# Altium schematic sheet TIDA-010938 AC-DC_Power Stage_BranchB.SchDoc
size 558 x 431 mm; Date: Not shown in title block; ApprovedBy: Not shown in title block; CheckedBy: Not shown in title block; Author: Not shown in title block; CompanyName: Not shown in title block; Engineer: Not shown in title block; Organization: Not shown in title block; Address1: Not shown in title block; Address2: Not shown in title block; Address3: Not shown in title block; Address4: Not shown in title block; DocumentNumber: 3; Revision: Use project parameter SCH_Rev; SheetNumber: 4; SheetTotal: 11; PageSetup: Record=PageOptions¦CenterHorizontal=True¦CenterVertical=True¦PrintScale=1.00¦XCorrection=1.00¦YCorrection=1.00¦PrintKind=0¦BorderSize=5000000¦LeftOffset=0¦BottomOffset=0¦Orientation=2¦PaperLength=1000¦PaperWidth=1000¦Scale=100¦PaperSource=15¦PrintQuality=600¦MediaType=1¦DitherType=10¦PaperKind=Letter¦PrintScaleMode=1
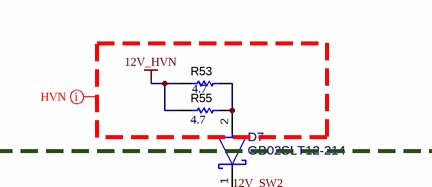
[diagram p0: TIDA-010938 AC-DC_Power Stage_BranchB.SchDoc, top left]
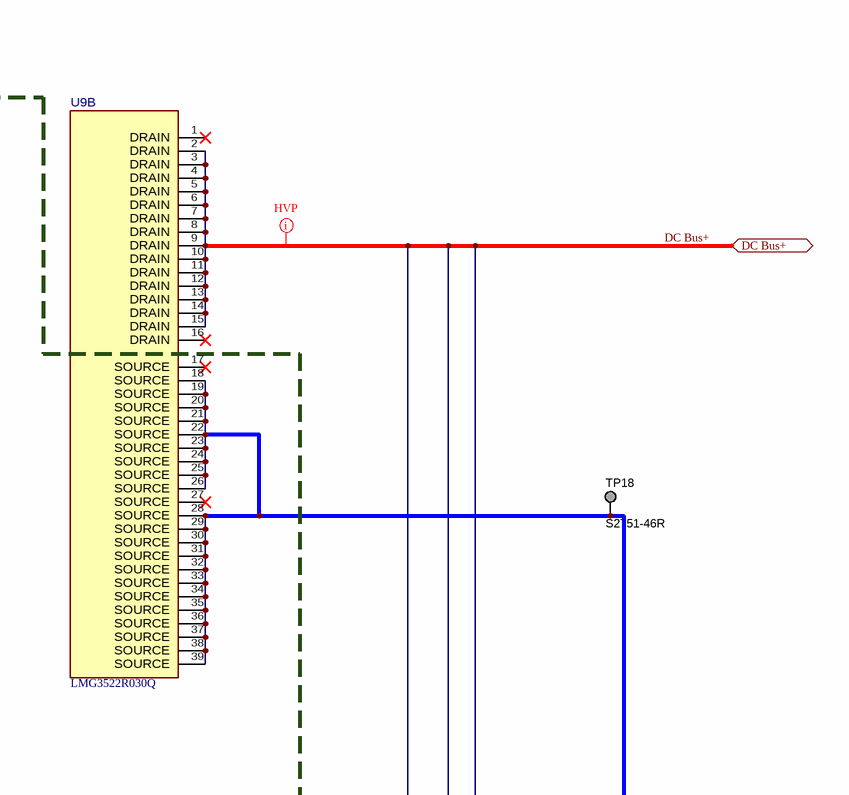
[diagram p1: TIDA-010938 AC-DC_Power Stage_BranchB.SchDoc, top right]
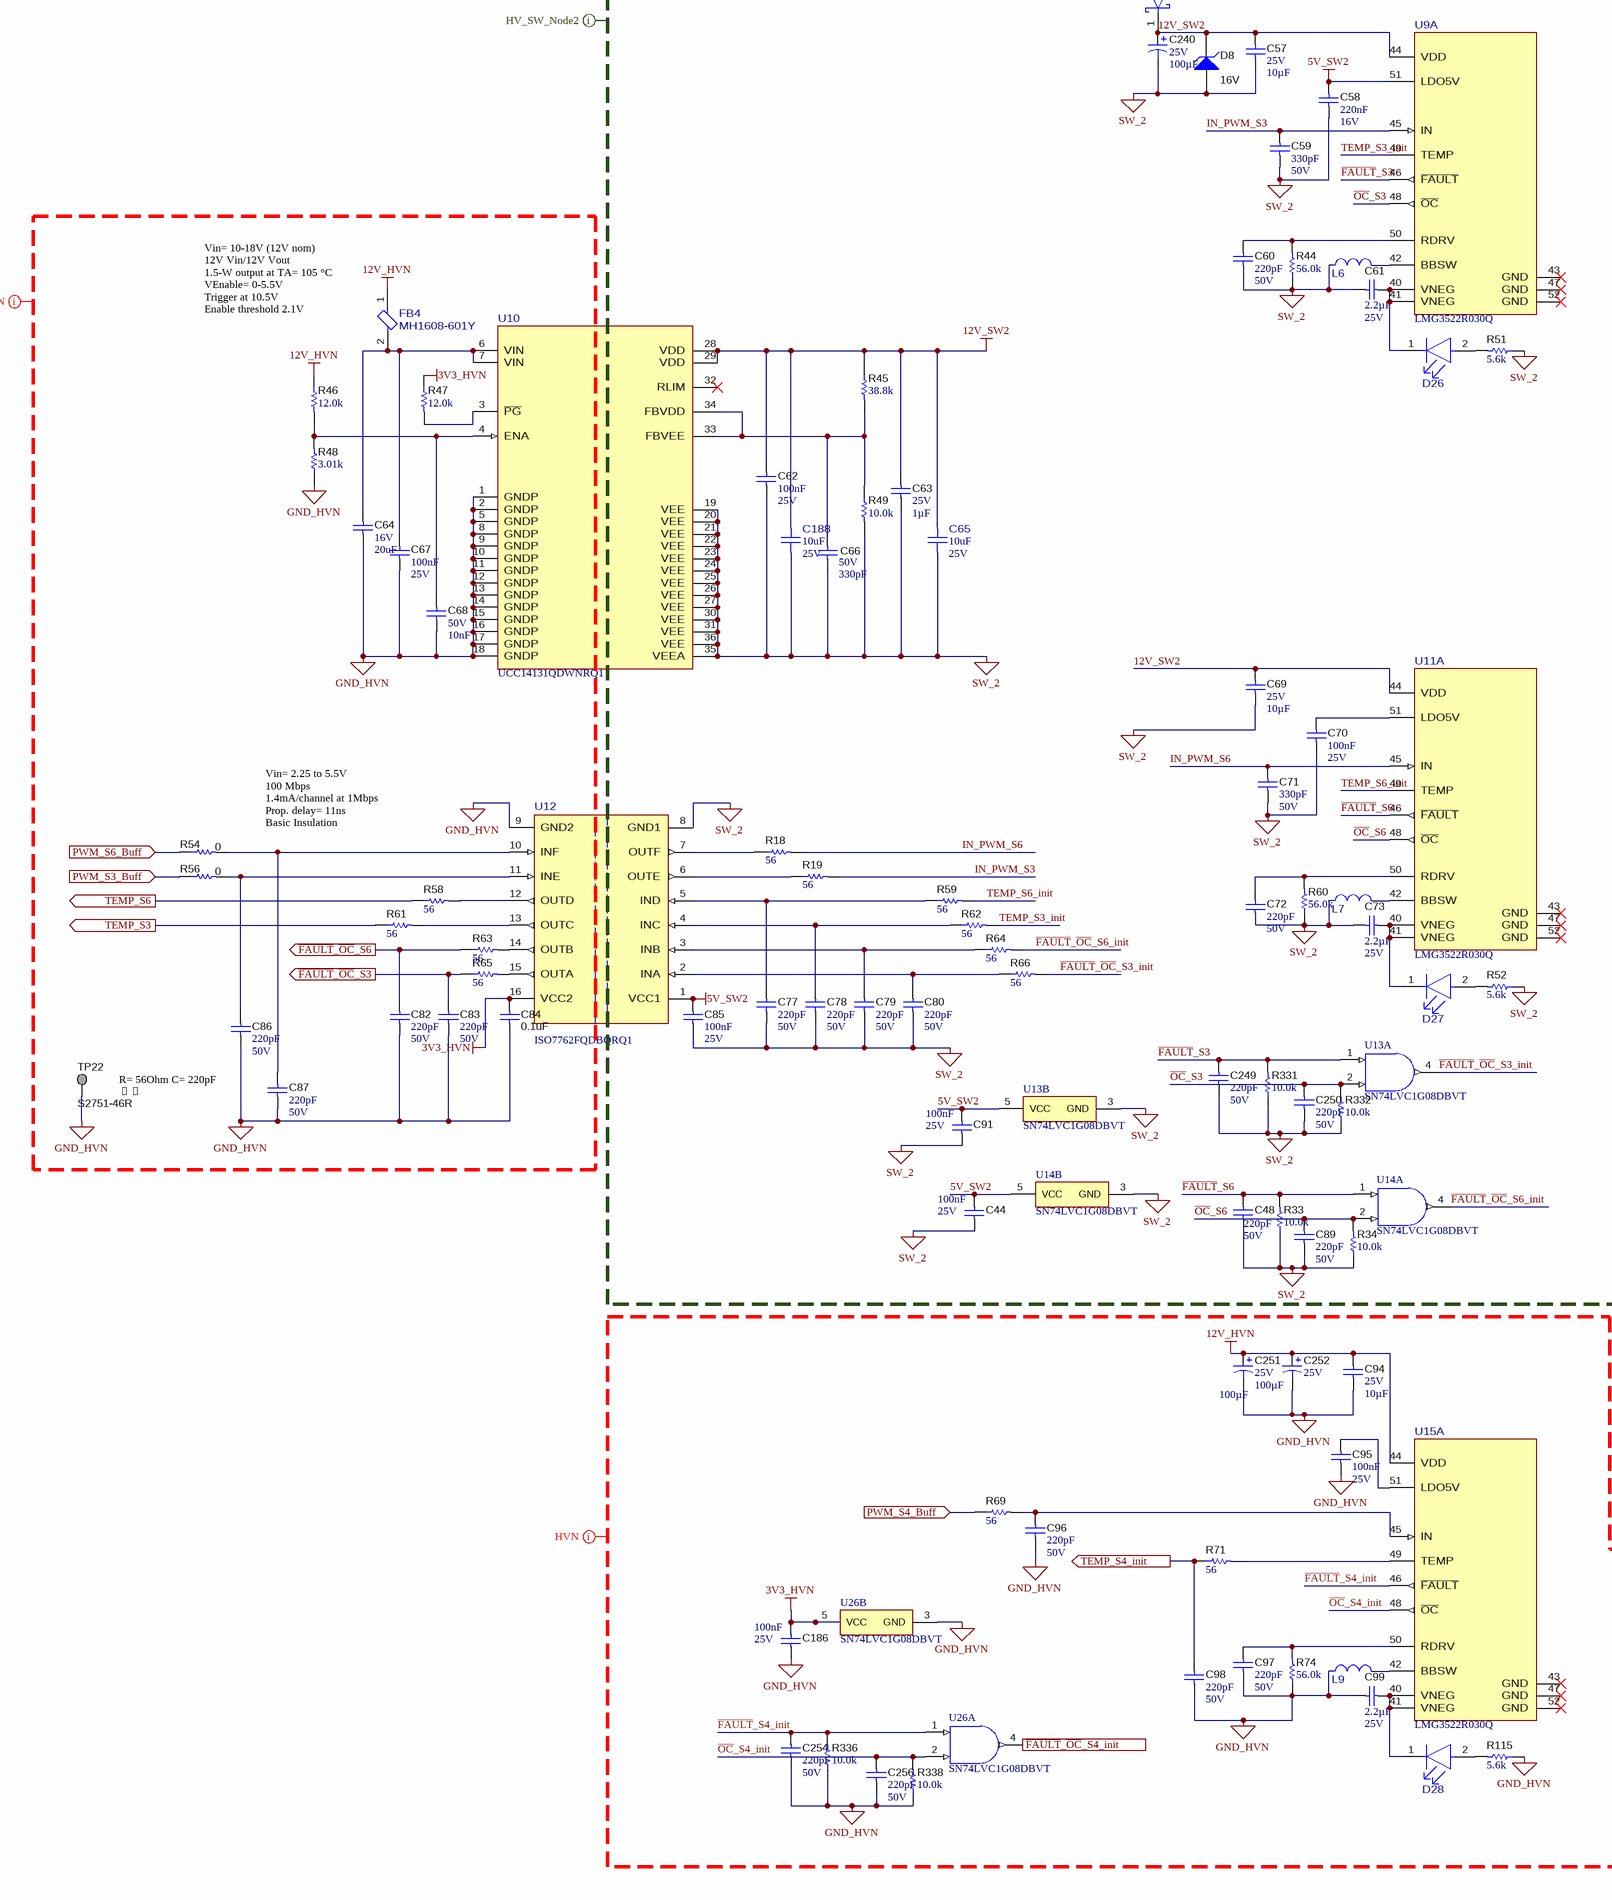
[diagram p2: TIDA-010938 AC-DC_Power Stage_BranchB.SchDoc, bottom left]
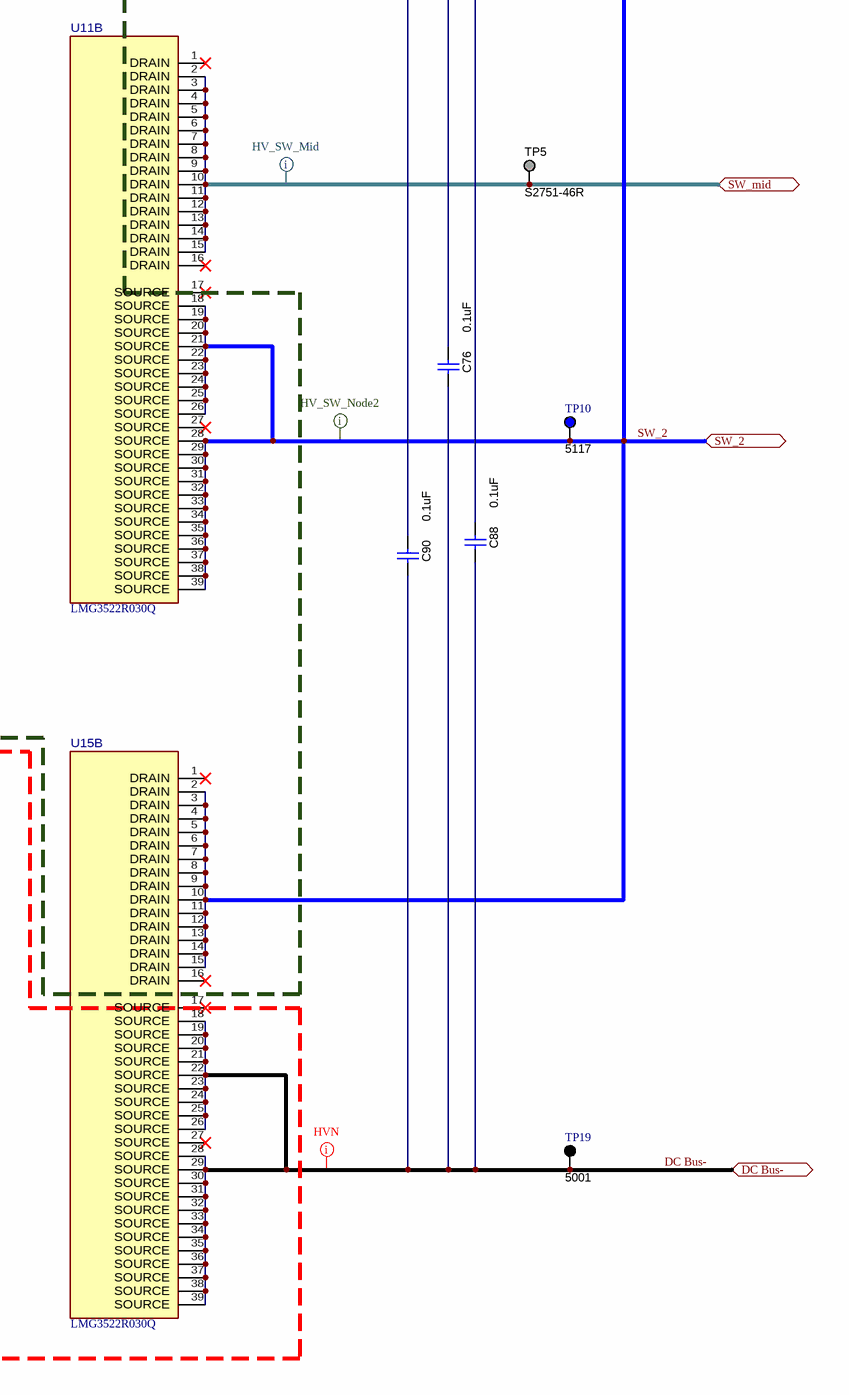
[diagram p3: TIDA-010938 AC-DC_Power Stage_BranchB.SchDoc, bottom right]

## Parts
C44  Cap_F: 100nF  VDC_V: 25V  [0603]  (hidden comment: 06033C104JAT2A)
C48  Cap_F: 220pF  VDC_V: 50V  [0603]  (hidden comment: GRM188R71H221KA01D)
C57  VDC_V: 25V  ValueDisplayed: 10µF  [1206_180]  (hidden comment: TMK316AB7106KLHT)
C58  Cap_F: 220nF  VDC_V: 16V  [0603]  (hidden comment: GRM188R71C224KA01D)
C59  Cap_F: 330pF  VDC_V: 50V  [0603]  (hidden comment: C0603C331K5RACTU)
C60  Cap_F: 220pF  VDC_V: 50V  [0603]  (hidden comment: GRM188R71H221KA01D)
C61  Cap_F: 2.2µF  VDC_V: 25V  [0805_HV]  (hidden comment: CGA4J3X7R1E225K125AB)
C62  Cap_F: 100nF  VDC_V: 25V  [0603]  (hidden comment: 06033C104JAT2A)
C63  VDC_V: 25V  ValueDisplayed: 1µF  [0603]  (hidden comment: TMK107BJ105KA-T)
C64  VDC_V: 16V  ValueDisplayed: 20uF  [0704]  (hidden comment: GRMJN7R61C206ME05)
C65  ValueDisplayed: 10uF  VDC_V: 25V  [FP-ZRB18AR61E106ME01L_0603-MFG]  (hidden comment: ZRB18AR61E106ME01L)
C66  VDC_V: 50V  ValueDisplayed: 330pF  [0603]  (hidden comment: GRM1885C1H331JA01D)
C67  Cap_F: 100nF  VDC_V: 25V  [0603]  (hidden comment: 06033C104JAT2A)
C68  VDC_V: 50V  Cap_F: 10nF  [0603]  (hidden comment: 885012206089)
C69  VDC_V: 25V  ValueDisplayed: 10µF  [1206_180]  (hidden comment: TMK316AB7106KLHT)
C70  Cap_F: 100nF  VDC_V: 25V  [0603]  (hidden comment: 06033C104JAT2A)
C71  Cap_F: 330pF  VDC_V: 50V  [0603]  (hidden comment: C0603C331K5RACTU)
C72  Cap_F: 220pF  VDC_V: 50V  [0603]  (hidden comment: GRM188R71H221KA01D)
C73  Cap_F: 2.2µF  VDC_V: 25V  [0805_HV]  (hidden comment: CGA4J3X7R1E225K125AB)
C76  ValueDisplayed: 0.1uF  [1812_254]  (hidden comment: C1812W104KDRACTU)
C77  Cap_F: 220pF  VDC_V: 50V  [0603]  (hidden comment: GRM188R71H221KA01D)
C78  Cap_F: 220pF  VDC_V: 50V  [0603]  (hidden comment: GRM188R71H221KA01D)
C79  Cap_F: 220pF  VDC_V: 50V  [0603]  (hidden comment: GRM188R71H221KA01D)
C80  Cap_F: 220pF  VDC_V: 50V  [0603]  (hidden comment: GRM188R71H221KA01D)
C82  Cap_F: 220pF  VDC_V: 50V  [0603]  (hidden comment: GRM188R71H221KA01D)
C83  Cap_F: 220pF  VDC_V: 50V  [0603]  (hidden comment: GRM188R71H221KA01D)
C84  ValueDisplayed: 0.1uF  [0603]  (hidden comment: 885012206095)
C85  Cap_F: 100nF  VDC_V: 25V  [0603]  (hidden comment: 06033C104JAT2A)
C86  Cap_F: 220pF  VDC_V: 50V  [0603]  (hidden comment: GRM188R71H221KA01D)
C87  Cap_F: 220pF  VDC_V: 50V  [0603]  (hidden comment: GRM188R71H221KA01D)
C88  ValueDisplayed: 0.1uF  [1812_254]  (hidden comment: C1812W104KDRACTU)
C89  Cap_F: 220pF  VDC_V: 50V  [0603]  (hidden comment: GRM188R71H221KA01D)
C90  ValueDisplayed: 0.1uF  [1812_254]  (hidden comment: C1812W104KDRACTU)
C91  Cap_F: 100nF  VDC_V: 25V  [0603]  (hidden comment: 06033C104JAT2A)
C94  VDC_V: 25V  ValueDisplayed: 10µF  [1206_180]  (hidden comment: TMK316AB7106KLHT)
C95  Cap_F: 100nF  VDC_V: 25V  [0603]  (hidden comment: 06033C104JAT2A)
C96  Cap_F: 220pF  VDC_V: 50V  [0603]  (hidden comment: GRM188R71H221KA01D)
C97  Cap_F: 220pF  VDC_V: 50V  [0603]  (hidden comment: GRM188R71H221KA01D)
C98  Cap_F: 220pF  VDC_V: 50V  [0603]  (hidden comment: GRM188R71H221KA01D)
C99  Cap_F: 2.2µF  VDC_V: 25V  [0805_HV]  (hidden comment: CGA4J3X7R1E225K125AB)
C186  Cap_F: 100nF  VDC_V: 25V  [0603]  (hidden comment: 06033C104JAT2A)
C188  ValueDisplayed: 10uF  VDC_V: 25V  [FP-ZRB18AR61E106ME01L_0603-MFG]  (hidden comment: ZRB18AR61E106ME01L)
C240  VDC_V: 25V  ValueDisplayed: 100µF  [UWT_630x770]  (hidden comment: UWT1E101MCL1GS)
C249  Cap_F: 220pF  VDC_V: 50V  [0603]  (hidden comment: GRM188R71H221KA01D)
C250  Cap_F: 220pF  VDC_V: 50V  [0603]  (hidden comment: GRM188R71H221KA01D)
C251  VDC_V: 25V  ValueDisplayed: 100µF  [UWT_630x770]  (hidden comment: UWT1E101MCL1GS)
C252  VDC_V: 25V  ValueDisplayed: 100µF  [UWT_630x770]  (hidden comment: UWT1E101MCL1GS)
C254  Cap_F: 220pF  VDC_V: 50V  [0603]  (hidden comment: GRM188R71H221KA01D)
C256  Cap_F: 220pF  VDC_V: 50V  [0603]  (hidden comment: GRM188R71H221KA01D)
D7  GB02SLT12-214  [FP-GB02SLT12-214_DO-214AA-MFG]
D8  value 16V  [SOD-123]  (hidden comment: BZT52C16-7-F)
D26  KG DELLS1.22-JGKH-24  [FP-KG DELLS1.22-JGKH-24_0603-MFG]  (value not drawn)
D27  KG DELLS1.22-JGKH-24  [FP-KG DELLS1.22-JGKH-24_0603-MFG]  (value not drawn)
D28  KG DELLS1.22-JGKH-24  [FP-KG DELLS1.22-JGKH-24_0603-MFG]  (value not drawn)
FB4  MH1608-601Y  [FP-MH1608-601Y_0603-MFG]
L6  SDEM20161T-4R7MS  [FP-SDEM20161T-4R7MS_SMD2-MFG]  (value not drawn)
L7  SDEM20161T-4R7MS  [FP-SDEM20161T-4R7MS_SMD2-MFG]  (value not drawn)
L9  SDEM20161T-4R7MS  [FP-SDEM20161T-4R7MS_SMD2-MFG]  (value not drawn)
R18  ValueDisplayed: 56  [0603]  (hidden comment: RG1608P-560-B-T5)
R19  ValueDisplayed: 56  [0603]  (hidden comment: RG1608P-560-B-T5)
R33  ValueDisplayed: 10.0k  [0603]  (hidden comment: RG1608P-103-B-T5)
R34  ValueDisplayed: 10.0k  [0603]  (hidden comment: RG1608P-103-B-T5)
R44  ValueDisplayed: 56.0k  [0603]  (hidden comment: RG1608P-563-B-T5)
R45  ValueDisplayed: 38.8k  [0603]  (hidden comment: RT0603DRE0738K8L)
R46  ValueDisplayed: 12.0k  [0603]  (hidden comment: ERJ-3EKF1202V)
R47  ValueDisplayed: 12.0k  [0603]  (hidden comment: ERJ-3EKF1202V)
R48  ValueDisplayed: 3.01k  [0603]  (hidden comment: RC0603FR-073K01L)
R49  ValueDisplayed: 10.0k  [0603]  (hidden comment: RG1608P-103-B-T5)
R51  ValueDisplayed: 5.6k  [0603]  (hidden comment: RC0603JR-075K6L)
R52  ValueDisplayed: 5.6k  [0603]  (hidden comment: RC0603JR-075K6L)
R53  ValueDisplayed: 4.7  [1206]  (hidden comment: CRCW12064R70JNEAHP)
R54  ValueDisplayed: 0  [0603]  (hidden comment: RCS06030000Z0EA)
R55  ValueDisplayed: 4.7  [1206]  (hidden comment: CRCW12064R70JNEAHP)
R56  ValueDisplayed: 0  [0603]  (hidden comment: RCS06030000Z0EA)
R58  ValueDisplayed: 56  [0603]  (hidden comment: RG1608P-560-B-T5)
R59  ValueDisplayed: 56  [0603]  (hidden comment: RG1608P-560-B-T5)
R60  ValueDisplayed: 56.0k  [0603]  (hidden comment: RG1608P-563-B-T5)
R61  ValueDisplayed: 56  [0603]  (hidden comment: RG1608P-560-B-T5)
R62  ValueDisplayed: 56  [0603]  (hidden comment: RG1608P-560-B-T5)
R63  ValueDisplayed: 56  [0603]  (hidden comment: RG1608P-560-B-T5)
R64  ValueDisplayed: 56  [0603]  (hidden comment: RG1608P-560-B-T5)
R65  ValueDisplayed: 56  [0603]  (hidden comment: RG1608P-560-B-T5)
R66  ValueDisplayed: 56  [0603]  (hidden comment: RG1608P-560-B-T5)
R69  ValueDisplayed: 56  [0603]  (hidden comment: RG1608P-560-B-T5)
R71  ValueDisplayed: 56  [0603]  (hidden comment: RG1608P-560-B-T5)
R74  ValueDisplayed: 56.0k  [0603]  (hidden comment: RG1608P-563-B-T5)
R115  ValueDisplayed: 5.6k  [0603]  (hidden comment: RC0603JR-075K6L)
R331  ValueDisplayed: 10.0k  [0603]  (hidden comment: RG1608P-103-B-T5)
R332  ValueDisplayed: 10.0k  [0603]  (hidden comment: RG1608P-103-B-T5)
R336  ValueDisplayed: 10.0k  [0603]  (hidden comment: RG1608P-103-B-T5)
R338  ValueDisplayed: 10.0k  [0603]  (hidden comment: RG1608P-103-B-T5)
TP5  S2751-46R  [Harwin_S2751-46R]  (no BOM)
TP10  5117  [Keystone5117]
TP18  S2751-46R  [Harwin_S2751-46R]  (no BOM)
TP19  5001  [Keystone5001]
TP22  S2751-46R  [Harwin_S2751-46R]  (no BOM)
U9  LMG3522R030Q  [RQS0052C-C01-MFG]  (parts A,B of 2)
U10  UCC14131QDWNRQ1  [DWJ0036A-MFG]
U11  LMG3522R030Q  [RQS0052C-C01-MFG]  (parts A,B of 2)
U12  ISO7762FQDBQRQ1  [DBQ0016A-MFG]
U13  SN74LVC1G08DBVT  [DBV0005A_N]  (parts A,B of 2)
U14  SN74LVC1G08DBVT  [DBV0005A_N]  (parts A,B of 2)
U15  LMG3522R030Q  [RQS0052C-C01-MFG]  (parts A,B of 2)
U26  SN74LVC1G08DBVT  [DBV0005A_N]  (parts A,B of 2)

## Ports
DC Bus+ (bidir), DC Bus- (bidir), PWM_S3_Buff (in), PWM_S4_Buff (in), PWM_S6_Buff (in), SW_2 (bidir), SW_mid (bidir), TEMP_S3 (out), TEMP_S4_init (out), TEMP_S6 (out), ~{FAULT}_~{OC}_S3 (out), ~{FAULT}_~{OC}_S4_init (out), ~{FAULT}_~{OC}_S6 (out)

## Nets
3V3_HVN: C84.2 C186.1 R47.1 U12.16(VCC2) U26.5(VCC)
5V_SW2: C44.1 C58.1 C85.2 C91.1 U9.51(LDO5V) U12.1(VCC1) U13.5(VCC) U14.5(VCC)
12V_HVN: C94.1 C251.1(+) C252.1(+) FB4.1 R46.1 R53.1 R55.1 U15.44(VDD)
12V_SW2: C57.1 C62.2 C63.2 C65.1 C69.1 C188.1 C240.1(+) D7.1(CATHODE) D8.1(K) R45.1 U9.44(VDD) U10.28(VDD) U10.29(VDD) U11.44(VDD)
GND_HVN: C64.1 C67.2 C68.1 C82.1 C83.1 C84.1 C86.1 C87.1 C94.2 C95.1 C96.1 C97.1 C98.1 C99.2 C186.2 C251.2(-) C252.2(-) C254.1 C256.1 L9.1 R48.1 R74.1 R115.1 R336.1 R338.1 TP22.1 U10.1(GNDP) U10.2(GNDP) U10.5(GNDP) U10.8(GNDP) U10.9(GNDP) U10.10(GNDP) U10.11(GNDP) U10.12(GNDP) U10.13(GNDP) U10.14(GNDP) U10.15(GNDP) U10.16(GNDP) U10.17(GNDP) U10.18(GNDP) U12.9(GND2) U26.3(GND)
SW_2: C44.2 C48.1 C57.2 C58.2 C59.1 C60.1 C61.2 C62.1 C63.1 C65.2 C66.2 C69.2 C70.1 C71.1 C72.1 C73.2 C77.1 C78.1 C79.1 C80.1 C85.1 C89.1 C91.2 C188.2 C240.2(-) C249.1 C250.1 D8.2(A) L6.1 L7.1 R33.1 R34.1 R44.1 R49.2 R51.1 R52.1 R60.1 R331.1 R332.1 TP10.1 TP18.1 U9.18(SOURCE) U9.19(SOURCE) U9.20(SOURCE) U9.21(SOURCE) U9.22(SOURCE) U9.23(SOURCE) U9.24(SOURCE) U9.25(SOURCE) U9.26(SOURCE) U9.28(SOURCE) U9.29(SOURCE) U9.30(SOURCE) U9.31(SOURCE) U9.32(SOURCE) U9.33(SOURCE) U9.34(SOURCE) U9.35(SOURCE) U9.36(SOURCE) U9.37(SOURCE) U9.38(SOURCE) U9.39(SOURCE) U10.19(VEE) U10.20(VEE) U10.21(VEE) U10.22(VEE) U10.23(VEE) U10.24(VEE) U10.25(VEE) U10.26(VEE) U10.27(VEE) U10.30(VEE) U10.31(VEE) U10.35(VEEA) U10.36(VEE) U11.18(SOURCE) U11.19(SOURCE) U11.20(SOURCE) U11.21(SOURCE) U11.22(SOURCE) U11.23(SOURCE) U11.24(SOURCE) U11.25(SOURCE) U11.26(SOURCE) U11.28(SOURCE) U11.29(SOURCE) U11.30(SOURCE) U11.31(SOURCE) U11.32(SOURCE) U11.33(SOURCE) U11.34(SOURCE) U11.35(SOURCE) U11.36(SOURCE) U11.37(SOURCE) U11.38(SOURCE) U11.39(SOURCE) U12.8(GND1) U13.3(GND) U14.3(GND) U15.2(DRAIN) U15.3(DRAIN) U15.4(DRAIN) U15.5(DRAIN) U15.6(DRAIN) U15.7(DRAIN) U15.8(DRAIN) U15.9(DRAIN) U15.10(DRAIN) U15.11(DRAIN) U15.12(DRAIN) U15.13(DRAIN) U15.14(DRAIN) U15.15(DRAIN) ; port SW_2
DC Bus+: C76.1 C88.1 C90.1 U9.2(DRAIN) U9.3(DRAIN) U9.4(DRAIN) U9.5(DRAIN) U9.6(DRAIN) U9.7(DRAIN) U9.8(DRAIN) U9.9(DRAIN) U9.10(DRAIN) U9.11(DRAIN) U9.12(DRAIN) U9.13(DRAIN) U9.14(DRAIN) U9.15(DRAIN) ; port DC Bus+
DC Bus-: C76.2 C88.2 C90.2 TP19.1 U15.18(SOURCE) U15.19(SOURCE) U15.20(SOURCE) U15.21(SOURCE) U15.22(SOURCE) U15.23(SOURCE) U15.24(SOURCE) U15.25(SOURCE) U15.26(SOURCE) U15.28(SOURCE) U15.29(SOURCE) U15.30(SOURCE) U15.31(SOURCE) U15.32(SOURCE) U15.33(SOURCE) U15.34(SOURCE) U15.35(SOURCE) U15.36(SOURCE) U15.37(SOURCE) U15.38(SOURCE) U15.39(SOURCE) ; port DC Bus-
~{FAULT}_~{OC}_S3: C83.2 R65.1 ; port ~{FAULT}_~{OC}_S3
~{FAULT}_~{OC}_S3_init: R66.2 U13.4(Y)
~{FAULT}_~{OC}_S4_init: U26.4(Y) ; port ~{FAULT}_~{OC}_S4_init
~{FAULT}_~{OC}_S6: C82.2 R63.1 ; port ~{FAULT}_~{OC}_S6
~{FAULT}_~{OC}_S6_init: R64.2 U14.4(Y)
~{FAULT}_S3: C249.2 R331.2 U9.46(~{FAULT}) U13.1(A)
~{FAULT}_S4_init: C254.2 R336.2 U15.46(~{FAULT}) U26.1(A)
~{FAULT}_S6: C48.2 R33.2 U11.46(~{FAULT}) U14.1(A)
IN_PWM_S3: C59.2 R19.2 U9.45(IN)
IN_PWM_S6: C71.2 R18.2 U11.45(IN)
~{OC}_S3: C250.2 R332.2 U9.48(~{OC}) U13.2(B)
~{OC}_S4_init: C256.2 R338.2 U15.48(~{OC}) U26.2(B)
~{OC}_S6: C89.2 R34.2 U11.48(~{OC}) U14.2(B)
PWM_S3_Buff: R56.1 ; port PWM_S3_Buff
PWM_S4_Buff: R69.1 ; port PWM_S4_Buff
PWM_S6_Buff: R54.1 ; port PWM_S6_Buff
SW_mid: TP5.1 U11.2(DRAIN) U11.3(DRAIN) U11.4(DRAIN) U11.5(DRAIN) U11.6(DRAIN) U11.7(DRAIN) U11.8(DRAIN) U11.9(DRAIN) U11.10(DRAIN) U11.11(DRAIN) U11.12(DRAIN) U11.13(DRAIN) U11.14(DRAIN) U11.15(DRAIN) ; port SW_mid
TEMP_S3: R61.1 ; port TEMP_S3
TEMP_S3_init: R62.2 U9.49(TEMP)
TEMP_S4_init: C98.2 R71.1 ; port TEMP_S4_init
TEMP_S6: R58.1 ; port TEMP_S6
TEMP_S6_init: R59.2 U11.49(TEMP)
NetC60_2: C60.2 R44.2 U9.50(RDRV)
NetC61_1: C61.1 D26.1(CATHODE) U9.40(VNEG) U9.41(VNEG)
NetC64_2: C64.2 C67.1 FB4.2 U10.6(VIN) U10.7(VIN)
NetC66_1: C66.1 R45.2 R49.1 U10.33(FBVEE) U10.34(FBVDD)
NetC68_2: C68.2 R46.2 R48.2 U10.4(ENA)
NetC70_2: C70.2 U11.51(LDO5V)
NetC72_2: C72.2 R60.2 U11.50(RDRV)
NetC73_1: C73.1 D27.1(CATHODE) U11.40(VNEG) U11.41(VNEG)
NetC77_2: C77.2 R59.1 U12.5(IND)
NetC78_2: C78.2 R62.1 U12.4(INC)
NetC79_2: C79.2 R64.1 U12.3(INB)
NetC80_2: C80.2 R66.1 U12.2(INA)
NetC86_2: C86.2 R56.2 U12.11(INE)
NetC87_2: C87.2 R54.2 U12.10(INF)
NetC95_2: C95.2 U15.51(LDO5V)
NetC96_2: C96.2 R69.2 U15.45(IN)
NetC97_2: C97.2 R74.2 U15.50(RDRV)
NetC99_1: C99.1 D28.1(CATHODE) U15.40(VNEG) U15.41(VNEG)
NetD7_2: D7.2(ANODE) R53.2 R55.2
NetD26_2: D26.2(ANODE) R51.2
NetD27_2: D27.2(ANODE) R52.2
NetD28_2: D28.2(ANODE) R115.2
NetL6_2: L6.2 U9.42(BBSW)
NetL7_2: L7.2 U11.42(BBSW)
NetL9_2: L9.2 U15.42(BBSW)
NetR18_1: R18.1 U12.7(OUTF)
NetR19_1: R19.1 U12.6(OUTE)
NetR47_2: R47.2 U10.3(~{PG})
NetR58_2: R58.2 U12.12(OUTD)
NetR61_2: R61.2 U12.13(OUTC)
NetR63_2: R63.2 U12.14(OUTB)
NetR65_2: R65.2 U12.15(OUTA)
NetR71_2: R71.2 U15.49(TEMP)

Not connected (* = marked no-connect by the designer): U9 1(DRAIN)* 16(DRAIN)* 17(SOURCE)* 27(SOURCE)* 43(GND)* 47(GND)* 52(GND)*; U10 32(RLIM)*; U11 1(DRAIN)* 16(DRAIN)* 17(SOURCE)* 27(SOURCE)* 43(GND)* 47(GND)* 52(GND)*; U15 1(DRAIN)* 16(DRAIN)* 17(SOURCE)* 27(SOURCE)* 43(GND)* 47(GND)* 52(GND)*

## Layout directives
net class HV_SW_Node2: 5V_SW2, 12V_HVN, 12V_SW2, GND_HVN, IN_PWM_S3, IN_PWM_S6, SW_2, TEMP_S3_init, TEMP_S6_init, ~{FAULT}_S3, ~{FAULT}_S6, ~{FAULT}_~{OC}_S3_init, ~{FAULT}_~{OC}_S6_init, ~{OC}_S3, ~{OC}_S6
net class HVN: 3V3_HVN, 5V_SW2, 12V_HVN, 12V_SW2, DC Bus-, GND_HVN, IN_PWM_S3, IN_PWM_S6, SW_2, TEMP_S3_init, TEMP_S6_init, ~{FAULT}_S3, ~{FAULT}_S6, ~{FAULT}_~{OC}_S3_init, ~{FAULT}_~{OC}_S6_init, ~{OC}_S3, ~{OC}_S6
net class HV_SW_Mid: SW_mid
net class HVP: DC Bus+

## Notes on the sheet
- (near FB4) Vin= 10-18V (12V nom)
  12V Vin/12V Vout
  1.5-W output at TA= 105 °C
  VEnable= 0-5.5V
  Trigger at 10.5V
  Enable threshold 2.1V
- Vin= 2.25 to 5.5V
  100 Mbps
  1.4mA/channel at 1Mbps
  Prop. delay= 11ns
  Basic Insulation
- R= 56Ohm C= 220pF
  𝜏= 1.23e-8

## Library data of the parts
C44 C62 C67 C70 C85 C91 C95 C186 = CMP-0006752-5: CAP, CERM, 0.1 uF, 25 V, +/- 5%, X7R, 0603; Manufacturer: AVX; TaMin_C: -55°C; ESR_ohm: 0.05; Polarized: N; SizeAreaWB_mm2: 4.68; Value1: 0.05 ohm; U/M: EA; Value: 0.1uF; TaMax_C: 125°C; SizeZ_mm: 1; SizeX_mm: 1.6; SizeY_mm: 0.8; SizeArea_mm2: 1.28; AEC Category: Q200
C48 C60 C72 C77-C80 C82 C83 C86 C87 C89 C96-C98 C249 C250 C254 C256 = CMP-0007442-5: CAP, CERM, 220 pF, 50 V, +/- 10%, X7R, 0603; Manufacturer: MuRata; TaMin_C: -55°C; Polarized: N; SizeAreaWB_mm2: 4.68; Value1: Unknown; U/M: EA; Value: 220pF; TaMax_C: 125°C; SizeZ_mm: 1; SizeX_mm: 1.6; SizeY_mm: 0.8; SizeArea_mm2: 1.28; AEC Category: Q200
C57 C69 C94 = CMP-0750154-1: CAP, CERM, 10 µF, 25 V,+/- 10%, X7R, AEC-Q200 Grade 1, 1206; Manufacturer: Taiyo Yuden; AEC Qualified: Y; SizeZ_mm: 1.8; TaMax_C: 125°C; TaMin_C: -55°C; Cap_Case: 1206; Polarized: N; AEC Grade: 1; SizeY_mm: 1.6; Value: 10uF; SizeX_mm: 3.2; SizeAreaWB_mm2: 10.92; AEC Category: Q200; U/M: EA; SizeArea_mm2: 5.12
C58 = CMP-0007389-4: CAP, CERM, 0.22 uF, 16 V, +/- 10%, X7R, 0603; Manufacturer: MuRata; TaMin_C: -55°C; Polarized: N; SizeAreaWB_mm2: 4.68; Value1: Unknown; U/M: EA; Value: 0.22uF; TaMax_C: 125°C; SizeZ_mm: 1; SizeX_mm: 1.6; SizeY_mm: 0.8; SizeArea_mm2: 1.28; AEC Category: Q200
C59 C71 = CMP-0006921-4: CAP, CERM, 330 pF, 50 V, +/- 10%, X7R, 0603; Manufacturer: Kemet; TaMin_C: -55°C; Polarized: N; SizeAreaWB_mm2: 4.68; Value1: Unknown; U/M: EA; Value: 330pF; TaMax_C: 125°C; SizeZ_mm: 1; SizeX_mm: 1.6; SizeY_mm: 0.8; SizeArea_mm2: 1.28; AEC Category: Q200
C61 C73 C99 = CMP-0007975-2: CAP, CERM, 2.2 uF, 25 V, +/- 10%, X7R, AEC-Q200 Grade 1, 0805; Manufacturer: TDK; TaMin_C: -55°C; Polarized: N; SizeAreaWB_mm2: 6.75; Value1: Unknown; U/M: EA; Value: 2.2uF; TaMax_C: 125°C; SizeZ_mm: 1.45; SizeX_mm: 2; SizeY_mm: 1.25; Cap_Case: 0805; SizeArea_mm2: 2.5; AEC Qualified: Y; AEC Grade: 1; AEC Category: Q200
C63 = CMP-0086152-1: CAP, CERM, 1 µF, 25 V,+/- 10%, X5R, 0603; Manufacturer: Taiyo Yuden; SizeAreaWB_mm2: 4.68; SizeZ_mm: 1; U/M: EA; Green_REACh: Passed; Value: 1uF; AEC Qualified: N; TaMax_C: 85°C; Green_Lifecycle: Active; AEC Category: Q200; SizeArea_mm2: 1.28; TaMin_C: -55°C; SizeY_mm: 0.8; SizeX_mm: 1.6
C64 = CMP-0009474-2: CAP, CERM, 20 uF, 16 V, +/- 20%, X5R, 0704; Manufacturer: MuRata; TaMin_C: -55°C; Polarized: N; SizeAreaWB_mm2: 5.6; Value1: Unknown; U/M: EA; Value: 20uF; TaMax_C: 85°C; SizeZ_mm: 0.8; SizeX_mm: 1; SizeY_mm: 1.8; Cap_F: 20µF; AEC Category: Q200
C65 C188 = CMP-0094458-1: 10µF ±20% 25V Ceramic Capacitor X5R 0603 (1608 Metric); Manufacturer: Murata Electronics; SizeZ_mm: 1.2mm; AEC Qualified: No
C66 = CMP-0007209-4: CAP, CERM, 330 pF, 50 V, +/- 5%, C0G/NP0, 0603; Manufacturer: MuRata; TaMin_C: -55°C; Polarized: N; SizeAreaWB_mm2: 4.68; Value1: Unknown; U/M: EA; Value: 330pF; TaMax_C: 125°C; SizeZ_mm: 1; SizeX_mm: 1.6; SizeY_mm: 0.8; SizeArea_mm2: 1.28; AEC Category: Q200
C68 = CMP-0750039-1: CAP, CERM, 0.01 µF, 50 V,+/- 10%, X7R, 0603; Manufacturer: Wurth Elektronik; Polarized: N; AEC Category: Q200; TaMax_C: 125°C; SizeAreaWB_mm2: 4.68; Value: 0.01uF; SizeArea_mm2: 1.28; SizeY_mm: 0.8; SizeZ_mm: 1; ValueDisplayed: 0.01µF; SizeX_mm: 1.6; U/M: EA; TaMin_C: -55°C
C76 C88 C90 = CMP-0009326-2: CAP, CERM, 0.1 uF, 1000 V, +/- 10%, X7R, 1812; Manufacturer: Kemet; Polarized: N; Value: 0.1uF; U/M: EA; Cap_F: 100nF; Value1: Unknown; VDC_V: 1kV; Value2: 1000V; TaMin_C: -55°C; TaMax_C: 125°C; Cap_Case: 1812; AEC Category: Q200; SizeArea_mm2: 14.4; SizeAreaWB_mm2: 23.1; SizeX_mm: 4.5; SizeY_mm: 3.2; SizeZ_mm: 2.54
C84 = CMP-0006837-4: CAP, CERM, 0.1 uF, 50 V, +/- 10%, X7R, 0603; Manufacturer: Wurth Elektronik; TaMin_C: -55°C; Polarized: N; SizeAreaWB_mm2: 4.68; Value1: Unknown; U/M: EA; Value: 0.1uF; TaMax_C: 125°C; SizeZ_mm: 1; SizeX_mm: 1.6; SizeY_mm: 0.8; Value2: 50V; SizeArea_mm2: 1.28; CompType: Capacitor; Cap_F: 100nF; AEC Category: Q200
C240 C251 C252 = CMP-0081462-1: CAP, AL, 100 µF, 25 V, +/- 20%, SMD; Manufacturer: Nichicon; TaMin_C: -55°C; Polarized: Y; SizeAreaWB_mm2: 77.4; U/M: EA; Value: 100uF; TaMax_C: 105°C; SizeZ_mm: 8; SizeX_mm: 7; SizeY_mm: 6.6; Cap_Case: 6.3x7.7mm; SizeArea_mm2: 46.2; CompType: Capacitor; AEC Qualified: N; IRMS_A: 91mA; AEC Category: Q200
D7 = CMP-0095009-1: Diode Silicon Carbide Schottky 1200 V 2A (DC) Surface Mount DO-214AA; Manufacturer: GeneSiC Semiconductor; Max Surge Forward Current: 20A; ValueDisplayed: 122pF; Vf_V: 1.2kV; Peak Reverse Current: 1uA; SizeZ_mm: 2.44mm; AEC Qualified: No; TJmax_C: 175°C
D8 = CMP-0005769-4: Diode, Zener, 16 V, 500 mW, AEC-Q101, SOD-123; Manufacturer: Diodes Inc.; SizeZ_mm: 1.35; AEC Qualified: Y; SizeX_mm: 3.85; AEC Category: Q101; Power_W: 500mW; SizeY_mm: 1.7; Value1: 0.5W; SizeAreaWB_mm2: 13.095; SizeArea_mm2: 6.545; RJA_CperW: 338
D26-D28 = CMP-0093310-1: Standard LEDs - SMD Green TOPLED E 1608; Manufacturer: Osram Opto; AEC Grade: Grade 2; LambdaP: 572nm; SizeZ_mm: 0.7mm; LuminousFlux_PhiV: 0.016-0.0295lm; Luminous Intensity: 4.5-9.7mcd; LambdaD: 570nm; Tjmax_C: 125°C; Angle: 120°; Led Orientation: Top View; Forward Current: 2mA; Vf_V: 1.8V; AEC Qualified: Yes; Vr_V: 12V
FB4 = CMP-0037505-1: 600 Ohms @ 100 MHz 1 Power, Signal Line Ferrite Bead 0603 (1608 Metric) 1A 200mOhm; Manufacturer: Bourns; DCR_ohm: 0.2; SizeZ_mm: 1mm; AEC Qualified: No; Impedance At Frequency: 600Ω @ 100MHz; Test Frequency: 100MHz; Tolerance_%: 25%
L6 L7 L9 = CMP-0089347-1: 4.7µH Unshielded Inductor 1.1A 426mOhm Max 0806 (2016 Metric); Manufacturer: Cyntec; AEC Qualified: No; Material: Metal Dust; Isat: 1.26A; Test Frequency: 1MHz; DCR_ohm: 0.426; SizeZ_mm: 1mm; Tolerance_%: 20%
R18 R19 R58 R59 R61-R66 R69 R71 = CMP-0023572-3: RES, 56, 0.1%, 0.1 W, 0603; Manufacturer: Susumu Co Ltd; Power_W: 100mW; TempCo: 25 ppm/C; Value_Code: 56R0; U/M: EA; Value: 56; SizeX_mm: 1.6; SizeY_mm: 0.8; SizeZ_mm: 1; Value2: 0.1W; SizeArea_mm2: 1.28; VDC_V: 75V; AEC Category: Q200
R33 R34 R331 R332 R336 R338 = CMP-0023404-3: RES, 10.0 k, 0.1%, 0.1 W, 0603; Manufacturer: Susumu Co Ltd; Power_W: 100mW; TempCo: 25 ppm/C; Value_Code: 10k0; U/M: EA; Value: 10.0k; EIA_Code: E192; Res_ohm: 10k; SizeX_mm: 1.6; SizeY_mm: 0.8; SizeZ_mm: 1; Value2: 0.1W; SizeArea_mm2: 1.28; VDC_V: 75V; AEC Category: Q200
R44 R60 R74 = CMP-0023577-3: RES, 56.0 k, 0.1%, 0.1 W, 0603; Manufacturer: Susumu Co Ltd; Power_W: 100mW; TempCo: 25 ppm/C; Value_Code: 56k0; U/M: EA; Value: 56.0k; Res_ohm: 56k; SizeX_mm: 1.6; SizeY_mm: 0.8; SizeZ_mm: 1; Value2: 0.1W; SizeArea_mm2: 1.28; VDC_V: 75V; AEC Category: Q200
R45 = CMP-0025200-2: RES, 38.8 k, 0.5%, 0.1 W, 0603; Manufacturer: Yageo America; Power_W: 100mW; TempCo: 50 ppm/C; Value_Code: 38k8; U/M: EA; Value: 38.8k; EIA_Code: E192; SizeX_mm: 1.6; SizeY_mm: 0.8; SizeZ_mm: 1; Value2: 0.1W; SizeArea_mm2: 1.28; VDC_V: 75V; AEC Category: Q200
R46 R47 = CMP-0022685-3: RES, 12.0 k, 1%, 0.1 W, 0603; Manufacturer: Panasonic; Power_W: 100mW; TempCo: 100 ppm/C; Value_Code: 12k0; U/M: EA; Value: 12.0k; Res_ohm: 12k; SizeX_mm: 1.6; SizeY_mm: 0.8; SizeZ_mm: 1; Value2: 0.1W; SizeArea_mm2: 1.28; VDC_V: 75V; AEC Category: Q200
R48 = CMP-0023076-5: RES, 3.01 k, 1%, 0.1 W, 0603; Manufacturer: Yageo; Power_W: 100mW; TempCo: 100 ppm/C; Value_Code: 3k01; Value: 3.01k; EIA_Code: E96; SizeX_mm: 1.6; SizeY_mm: 0.8; SizeZ_mm: 1; Value2: 0.1W; SizeArea_mm2: 1.28; AEC Qualified: N; VDC_V: 75V; AEC Category: Q200; SizeAreaWB_mm2: 4.68
R49 = CMP-0023404-1: RES, 10.0 k, 0.1%, 0.1 W, 0603; Manufacturer: Susumu Co Ltd; Power_W: 100mW; TempCo: 25 ppm/C; Value_Code: 10k0; U/M: EA; Value: 10.0k; EIA_Code: E192; Res_ohm: 10k; SizeX_mm: 1.6; SizeY_mm: 0.8; SizeZ_mm: 1; Value2: 0.1W; SizeArea_mm2: 1.28; VDC_V: 75V; AEC Category: Q200
R51 R52 R115 = CMP-0025933-5: RES, 5.6 k, 5%, 0.1 W, 0603; Manufacturer: Yageo; Power_W: 100mW; TempCo: 100 ppm/C; Value_Code: 5k60; Value: 5.6k; EIA_Code: E24; SizeX_mm: 1.6; SizeY_mm: 0.8; SizeZ_mm: 1; Value2: 0.1W; SizeArea_mm2: 1.28; AEC Qualified: N; VDC_V: 75V; AEC Category: Q200; SizeAreaWB_mm2: 4.68
R53 R55 = CMP-0018694-3: RES, 4.7, 5%, 0.75 W, AEC-Q200 Grade 0, 1206; Manufacturer: Vishay-Dale; Power_W: 750mW; TempCo: 200 ppm/C; Value_Code: 4R70; Value: 4.7; EIA_Code: E24; SizeX_mm: 3.2; SizeY_mm: 1.6; SizeZ_mm: 1.35; Value2: 0.75W; SizeArea_mm2: 5.12; AEC Qualified: Y; AEC Grade: 0; AEC Category: Q200
R54 R56 = CMP-0081973-1: RES, 0, 0%, 0.25 W, AEC-Q200 Grade 0, 0603; Manufacturer: Vishay-Dale; SizeAreaWB_mm2: 4.68; SizeArea_mm2: 1.28; AEC Qualified: Y; AEC Category: Q200; Value: 0; SizeZ_mm: 1; SizeY_mm: 0.8; Power_W: 250mW; Value2: 0.25W; SizeX_mm: 1.6
TP5 TP18 TP22 = CMP-0003968-1: Test Point, SMT; Manufacturer: Harwin
TP10 = CMP-0055154-1: Test Point, Miniature, Blue, TH; Manufacturer: Keystone; CNHeader: FALSE; Green_Lifecycle: Active; Green_REACh: Passed; ContactFinish: Silver; CT: TRUE
TP19 = CMP-0055138-2: Test Point, Miniature, Black, TH; Manufacturer: Keystone Electronics; ContactFinish: Silver; CNHeader: FALSE; Green_Lifecycle: Active; Green_REACh: Passed; CT: TRUE
U9 U11 U15 = CMP-0089967-3: 650-V 30-mΩ GaN FET with Integrated Driver and Protection; Manufacturer: Texas Instruments; Standoff Height: 0mm; TJmax_C: +125°C; AEC Qualified: Yes; Nominal Supply Current: 16mA; Min Supply Voltage: 7.5V; SizeZ_mm: 1mm; AEC Category: Q200; Output Voltage: 520V; CompType: IC; Number Of Outputs: 1; Max Supply Voltage: 18V; AEC Grade: Grade 1
U10 = CMP-0033793-2: Automotive 1.5-W, 12-V VIN / 12-VOUT, 15-V VIN / 15-V VOUT, HighDensity, > 5-kVRMS, Isolated DC/DC Module; Manufacturer: Texas Instruments; SizeZ_mm: 3.55mm; AEC Qualified: Yes; AEC Grade: Grade 1; Max Supply Voltage: 18V; Min Supply Voltage: 9V; Nominal Supply Current: 200-270mA; Number Of Outputs: 2; Output Type: AdjustableProgrammable; Output Voltage: 10-18V; Standoff Height: 0.1mm; Switching Frequency: 18MHz; TaMax_C: +125°C; TaMin_C: -40°C; TJmax_C: +150°C; AEC Category: Q200; CompType: IC
U12 = CMP-0091060-1: Automotive, robust EMC, six-channel, 4/2, reinforced digital isolator 16-SSOP -40 to 125; Manufacturer: Texas Instruments; AEC Qualified: Yes; AEC Grade: Grade 1; Standoff Height: 0.11mm; Min Supply Voltage: 2.25V; SizeZ_mm: 1.75mm; TaMax_C: +125°C; Nominal Supply Current: 2.1-25.7mA; TJmax_C: +150°C; Max Supply Voltage: 5.5V; TaMin_C: -40°C
U13 U14 U26 = CMP-0051571-2: Single 2-Input Positive-AND Gate, DBV0005A, SMALL T&R; Manufacturer: Texas Instruments; Voltage(Nom)(V): 1.8,2.5,3.3,5; Bits(#): 1; Rating: Catalog; F @ Nom Voltage(Max)(Mhz): 150; 3-State Output: No; Gate Type: AND; Output Drive (IOL/IOH)(Max)(mA): 32/-32; Technology Family: LVC; Logic: True; VCC(Max)(V): 5.5; ICC @ Nom Voltage(Max)(mA): 0.01; VCC(Min)(V): 1.65; tpd @ Nom Voltage(Max)(ns): 4.5,6,4,5; Input Type: CMOS/TTL; Output Type: CMOS; AEC Category: Q200; AEC Qualified: N; CompType: IC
